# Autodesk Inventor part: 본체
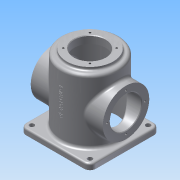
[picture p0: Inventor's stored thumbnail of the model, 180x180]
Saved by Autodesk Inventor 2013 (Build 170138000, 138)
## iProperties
Created: 2015-10
Part Number: 본체
Material: 알루미늄 6061
Document SubType Name: Modeling
Designer: Administrator
Density: 2.71 g/cm^3
Mass: 985.994 g
Surface Area: 1037.38 cm^2
Volume: 363.835 cm^3
Author: Administrator
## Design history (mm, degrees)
sketch "스케치1"
  geometry: L1 (-50, 60)-(50, 60); L2 (60, 50)-(60, -50); L3 (50, -60)-(-50, -60); L4 (-60, -50)-(-60, 50); A1 r 10 centre (-50, 50) between (-50, 60) and (-60, 50); A2 r 10 centre (-50, -50) between (-60, -50) and (-50, -60); A3 r 10 centre (50, -50) between (50, -60) and (60, -50); A4 r 10 centre (50, 50) between (60, 50) and (50, 60); 5 further points
  constraints: 8 end point, 8 point on circle, 8 tangent, 4 centre point, 4 point on line, 3 equal radius, 2 midpoint, 2 parallel, 2 perpendicular, 1 horizontal, 1 horizontal alignment, 1 vertical alignment
  dimensions: "d0" = 120 distance of point (-60, 60) point (60, 60); "d2" = 10 radius of A1
extrude "돌출1" new body sketch "스케치1" distance "d4" = 10; taper "d5" = 0 deg
sketch "스케치2"
  geometry: C1 r 50 at (0, 0); 1 further point
  constraints: 1 centre point, 1 coincident
  dimensions: "d6" = 100 diameter of C1
extrude "돌출2" join sketch "스케치2" distance "d8" = 110; taper "d9" = 0 deg
sketch "스케치3"
  geometry: C1 r 40 at (0, 0); 1 further point
  constraints: 1 centre point, 1 coincident
  dimensions: "d10" = 80 diameter of C1
extrude "돌출3" join sketch "스케치3" distance "d12" = 5; taper "d13" = 0 deg
sketch "스케치4"
  geometry: C1 r 40 at (0, 60); 1 further point
  constraints: 1 centre point, 1 vertical alignment
  dimensions: "d14" = 80 diameter of C1; "d16" = 60 distance of C1.centre point (0, 0)
extrude "돌출4" join sketch "스케치4" stored distance "d17" = 124; taper "d18" = 0 deg
hole "구멍1" diameter "d21" = 54; stored, may be unused: countersink angle "d25" = 90 deg, drill point angle "d27" = 118 deg; dims "d19" = 10, "d20" = 10, "d22" = 6, "d23" = 90, "d24" = 112, "d26" = 8
hole "구멍2" diameter "d30" = 54; stored, may be unused: countersink angle "d34" = 90 deg, drill point angle "d36" = 118 deg; dims "d28" = 10, "d29" = 10, "d31" = 6, "d32" = 90, "d33" = 112, "d35" = 8
sketch "스케치5"
  geometry: C1 r 27 at (0, 0) reference; 2 further points
  constraints: 1 horizontal alignment
  dimensions: "d37" = 32.5 distance of point (32.5, 0) C1.centre
hole "구멍3" sketch "스케치5" at (32.5, 0) diameter "d38" = 3.242; stored, may be unused: countersink angle "d42" = 90 deg, drill point angle "d44" = 118 deg; dims "d39" = 8, "d40" = 90, "d41" = 112, "d43" = 10
sketch "스케치6"
  geometry: A1 r 32.5 centre (0, 0) between (-22.981, 22.981) and (22.981, 22.981); 3 further points
  constraints: 4 point on circle, 2 horizontal alignment, 2 vertical alignment, 1 centre point, 1 coincident
  dimensions: "d48" = 65 diameter of A1; "d49" = 90 deg dimension on point (0, 0) A1.end A1.start
hole "구멍4" sketch "스케치6" at (-22.981, 22.981), (22.981, 22.981), (22.981, -22.981), (-22.981, -22.981) diameter "d51" = 3.242; stored, may be unused: countersink angle "d55" = 90 deg, drill point angle "d57" = 118 deg; dims "d52" = 8, "d53" = 90, "d54" = 112, "d56" = 10
hole "구멍5" diameter "d60" = 8; stored, may be unused: countersink angle "d64" = 90 deg, drill point angle "d66" = 0 deg; dims "d58" = 10, "d59" = 10, "d61" = 8, "d62" = 90, "d63" = 112, "d65" = 20
hole "구멍6" diameter "d69" = 8; stored, may be unused: countersink angle "d73" = 90 deg, drill point angle "d75" = 0 deg; dims "d67" = 10, "d68" = 10, "d70" = 8, "d71" = 90, "d72" = 112, "d74" = 20
hole "구멍7" diameter "d78" = 8; stored, may be unused: countersink angle "d82" = 90 deg, drill point angle "d84" = 0 deg; dims "d76" = 10, "d77" = 10, "d79" = 8, "d80" = 90, "d81" = 112, "d83" = 20
hole "구멍8" diameter "d87" = 8; stored, may be unused: countersink angle "d91" = 90 deg, drill point angle "d93" = 0 deg; dims "d85" = 10, "d86" = 10, "d88" = 8, "d89" = 90, "d90" = 112, "d92" = 20
node "작업 평면1"
sketch "스케치7"
  geometry: L1 (-3.602, 31.245)-(-3.602, 88.755); L2 (-3.602, 88.755)-(3.602, 88.755); L3 (3.602, 88.755)-(3.602, 31.245); L4 (3.602, 31.245)-(-3.602, 31.245); L5 (-50, -10)-(50, -10) reference; 5 further points
  constraints: 3 midpoint, 2 vertical alignment, 1 horizontal alignment, 2 other
  dimensions: "d105" = 70 distance of point (0, 60) point (0, -10)
feature "엠보싱1" sketch "스케치7" dims "d0" = 120, "d2" = 10, "d94" = 0.5, "d95" = 0
chamfer "모따기1" distance "d96" = 3; stored, may be unused: second distance "d97" = 2, angle "d98" = 45 deg
chamfer "모따기2" distance "d99" = 1; stored, may be unused: second distance "d100" = 2, angle "d101" = 45 deg
fillet "모깎기4" dims "d106" = 5
fillet "모깎기5" dims "d107" = 5
fillet "모깎기6" dims "d108" = 3
fillet "모깎기2" dims "d103" = 3
fillet "모깎기3" dims "d104" = 3
fillet "모깎기7" dims "d109" = 3
node "솔리드1"
pattern_circular "원형 패턴1" dims angle "d46" = 360 deg
mirror "대칭1"
